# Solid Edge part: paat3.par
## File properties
Author: Mac
Template: Normal.par
Last saved by: Mac
Revision: 31
Application: Solid Edge
Material: Epoxy, cast rigid
Face Style: White
Fill Style: ANSI34(Plastic)
Virtual Style: Shiny resin yellow
Coef. of Thermal Exp: 5.9e-05
Thermal Conductivity: 2.1
Specific Heat: 0.0
Modulus of Elasticity: 3102640650.0
Poission's Ratio: 0.37
Yield Stress: 65500191.5
Ultimate Stress: 0.0
Elongation: 0.0
Density: 1300,000 kg/m^3
Accuracy: 0,990
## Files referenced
%..\..\Copy of copy of paat3\Asm15.asm
EC:\Documents and Settings\Mac\Desktop\Copy of copy of paat3\Asm15.asm
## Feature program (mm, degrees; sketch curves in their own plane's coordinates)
make body feature "unnamed MakeBodyFeature 1"
sketch for "ExtrudedProtrusion_1" plane through (11.3044, 0, -19.7548) normal (0, -1, 0) x-axis (1, 0, 0)
extrude "ExtrudedProtrusion_1" add finite 0.5 along +normal
sketch for "unnamed Cutout 1" plane through (12.2548, -0.5, -19.755) normal (0, -1, 0) x-axis (1, 0, 0)
extrude "unnamed Cutout 1" cut through along -normal
sketch for "ExtrudedCutout_5" plane through (11.3053, -0.5, -19.755) normal (0, -1, 0) x-axis (1, 0, 0)
extrude "ExtrudedCutout_5" cut finite 22 along -normal
sketch for "unnamed Cutout 2" plane through (-96.2523, 0, 0) normal (1, 0, 0) x-axis (0, 1, 0)
extrude "unnamed Cutout 2" cut along +normal
sketch for "unnamed Cutout 3" plane through (-96.2523, 0, 0) normal (1, 0, 0) x-axis (0, 1, 0)
extrude "unnamed Cutout 3" cut along +normal
sketch for "ExtrudedProtrusion_5" plane through (14.9994, 18.5539, 0) normal (0, 0, 1) x-axis (1, 0, 0)
extrude "ExtrudedProtrusion_5" add finite 0.2 along -normal
thinwall "Thinwall_9"  Thickness = 0.4 mm
sketch for "ExtrudedCutout_9" plane through (-89.4756, 0, 0) normal (1, 0, 0) x-axis (0, 1, 0)
extrude "ExtrudedCutout_9" cut finite 14.274 symmetric
sketch for "unnamed Cutout 4" plane through (-78.7952, 10.7, -24.5412) normal (0.989016, 0, 0.147809) x-axis (0, 1, 0)
  line (0.35, -2.7892) -> (0.35, -0.2935)
  arc centre (-0.99, -0.2935) radius 1.34 from (0.35, -0.2935) to (0.142, 0.4236) ccw
  arc centre (7.39, -0.2935) radius 1.34 from (6.258, 0.4236) to (6.05, -0.2935) ccw
  line (6.05, -2.7892) -> (6.05, -0.2935)
extrude "unnamed Cutout 4" cut through along -normal
body pattern "unnamed BodyPattern 1"
pattern "unnamed Pattern 1"
web network "WebNetwork_8"  Thickness = 0.4 mm
web network "WebNetwork_10"  Profile_Plane1_Distance = 27.6 mm; Thickness = 0.4 mm
sketch for "ExtrudedProtrusion_7" plane through (95.3651, -0.5, -15.3074) normal (0.9981, 0, -0.06161) x-axis (0, 1, 0)
extrude "ExtrudedProtrusion_7" add finite 0.4 along -normal
sketch for "ExtrudedCutout_14" plane through (-9.8993, 20.268, 8.0334) normal (-0.996876, 0, 0.078981) x-axis (0, -1, 0)
extrude "ExtrudedCutout_14" cut finite 8.6517 symmetric
web network "WebNetwork_11"  Profile_Plane1_Distance = 4 mm; Thickness = 1 mm
web network "WebNetwork_12"  Profile_Plane1_Distance = 2 mm; Thickness = 0.4 mm
web network "WebNetwork_13"  Profile_Plane1_Distance = 4 mm; Thickness = 1 mm
web network "WebNetwork_14"  Thickness = 1 mm; Profile_Plane1_Distance = 4 mm
sketch for "ExtrudedProtrusion_9" plane through (42.2932, -0.5, -28.6294) normal (0.06161, 0, 0.9981) x-axis (0, 1, 0)
  bspline degree 3 poles (-26.765, 35.525) (-25.9166, 30.6262) (-24.9611, 25.7482) (-22.7557, 16.0123) (-21.5039, 11.1594) (-19.3196, 3.9687) (-18.5369, 1.5903) (-16.8243, -3.1171) (-15.8984, -5.4454) (-14.3989, -8.89) (-13.88, -10.0297) (-12.8195, -12.2993) (-12.2779, -13.4293) (-11.2006, -15.693) (-10.6654, -16.827) (-9.646, -19.0945) (-9.1605, -20.2278) (-8.7078, -21.375) knots 0 0.2488 0.4996 0.625 0.7504 0.813 0.8757 0.9384 1 multiplicities 4 2 2 2 2 2 2 2 4
  line (-8.7078, -21.375) -> (8.7078, -21.375)
  bspline degree 3 poles (8.7078, -21.375) (9.1589, -20.2318) (9.6428, -19.1019) (10.1474, -17.9793) (10.6613, -16.836) (11.1969, -15.7009) (12.2754, -13.4345) (12.8178, -12.3029) (13.8789, -10.0321) (14.3977, -8.8927) (15.8947, -5.4541) (16.8174, -3.1346) (18.5242, 1.5539) (19.3052, 3.9242) (21.4857, 11.0943) (22.7397, 15.9462) (24.9544, 25.714) (25.9137, 30.6095) (26.765, 35.525) knots 0 0.2078 0.2608 0.3137 0.3666 0.4725 0.5783 0.79 1 multiplicities 4 3 2 2 2 2 2 2 4
  line (26.765, 35.525) -> (-26.765, 35.525)
extrude "ExtrudedProtrusion_9" add finite 0.4 along +normal
sketch for "unnamed Protrusion 1" #1 plane through (-2.0037, -0.5, -17.8799) normal (0.06161, 0, 0.9981) x-axis (0, 1, 0)
  line (28.15, 4.1934) -> (20.15, 4.1934)
  line (20.15, 4.1934) -> (20.15, -3.8066)
  line (20.15, -3.8066) -> (28.15, -3.8066)
  line (28.15, -3.8066) -> (28.15, 4.1934)
sketch for "unnamed Protrusion 1" #2 plane through (-2.0037, -0.5, -17.8799) normal (0.06161, 0, 0.9981) x-axis (0, 1, 0)
  line (-28.15, 4.2453) -> (-20.15, 4.2453)
  line (-20.15, 4.2453) -> (-20.15, -3.7547)
  line (-20.15, -3.7547) -> (-28.15, -3.7547)
  line (-28.15, -3.7547) -> (-28.15, 4.2453)
sketch for "unnamed Protrusion 1" #3 plane through (-2.0037, -0.5, -17.8799) normal (0.06161, 0, 0.9981) x-axis (0, 1, 0)
  line (13.55, 8.15) -> (-12.55, 8.15)
  line (-12.55, 8.15) -> (-12.55, -8.15)
  line (-12.55, -8.15) -> (13.55, -8.15)
  line (13.55, -8.15) -> (13.55, 8.15)
sketch for "unnamed Protrusion 1" #4 plane through (-2.0037, -0.5, -17.8799) normal (0.06161, 0, 0.9981) x-axis (0, 1, 0)
  line (31.8898, 9.35) -> (-31.8898, 9.35)
  bspline degree 3 poles (-31.8898, 9.35) (-31.494, 3.1414) (-30.9994, -3.0593) (-30.38, -9.25) knots 0 1 multiplicities 4 4
  line (30.38, -9.25) -> (-30.38, -9.25)
  bspline degree 3 poles (30.38, -9.25) (30.9994, -3.0593) (31.494, 3.1414) (31.8898, 9.35) knots 0 1 multiplicities 4 4
extrude "unnamed Protrusion 1" add finite 0.4 along +normal
sketch for "ExtrudedCutout_15" plane through (-53.1152, -0.5, -22.7401) normal (0.06161, 0, 0.9981) x-axis (0, 1, 0)
  line (13.55, -26.965) -> (-13.55, -26.965)
  line (-13.55, -26.965) -> (-13.55, -27.965)
  line (13.55, -27.965) -> (-13.55, -27.965)
  line (13.55, -26.965) -> (13.55, -27.965)
extrude "ExtrudedCutout_15" cut finite 6.11 along -normal
sketch for "unnamed Protrusion 2" plane through (-26.0789, -0.5, -30.5306) normal (0.06161, 0, 0.9981) x-axis (0, 1, 0)
  line (-13.55, 13.5) -> (-13.55, -13.6)
  line (-13.55, -13.6) -> (13.55, -13.6)
  line (13.55, 13.5) -> (13.55, -13.6)
  line (-13.55, 13.5) -> (13.55, 13.5)
extrude "unnamed Protrusion 2" add finite 0.4 along +normal
sketch for "unnamed Protrusion 3" #1 plane through (-38.2095, -0.5, -7.9303) normal (0.9981, 0, -0.06161) x-axis (0, 1, 0)
  bspline degree 3 poles (-29.8105, -17.9296) (-28.9987, -18.4378) (-28.1501, -18.8727) (-26.4544, -19.6431) (-25.6087, -19.9798) (-24.75, -20.2908) knots 0 0.5126 1 multiplicities 4 2 4
  line (-24.75, -15.7) -> (-24.75, -20.2908)
  line (-24.75, -15.7) -> (-24.75, 12.8808)
  line (-35.7137, 12.8808) -> (-24.75, 12.8808)
  bspline degree 3 poles (-35.7137, 12.8808) (-34.435, 2.7396) (-32.9833, -7.3799) (-31.2723, -17.4567) knots 0 1 multiplicities 4 4
  line (-30.5225, -17.4567) -> (-31.2723, -17.4567)
  arc centre (-21.3939, -4.4843) radius 15.8623 from (-30.5225, -17.4567) to (-29.8105, -17.9296) ccw
sketch for "unnamed Protrusion 3" #2 plane through (-38.2095, -0.5, -7.9303) normal (0.9981, 0, -0.06161) x-axis (0, 1, 0)
  bspline degree 3 poles (29.8105, -17.9296) (28.9987, -18.4378) (28.1501, -18.8727) (26.4544, -19.6431) (25.6087, -19.9798) (24.75, -20.2908) knots 0 0.5126 1 multiplicities 4 2 4
  line (24.75, -15.7) -> (24.75, -20.2908)
  line (24.75, -15.7) -> (24.75, 12.8808)
  line (24.75, 12.8808) -> (35.7137, 12.8808)
  bspline degree 3 poles (35.7137, 12.8808) (34.435, 2.7396) (32.9833, -7.3799) (31.2723, -17.4567) knots 0 1 multiplicities 4 4
  line (30.5225, -17.4567) -> (31.2723, -17.4567)
  arc centre (21.3939, -4.4843) radius 15.8623 from (30.5225, -17.4567) to (29.8105, -17.9296) cw
extrude "unnamed Protrusion 3" add finite 0.4 along +normal
sketch for "ExtrudedCutout_16" #1 plane through (-33.8579, 0, 0) normal (1, 0, 0) x-axis (0, 1, 0)
  line (-35.9773, 0) -> (-34.6634, 4.9035)
  line (-29.2434, 4.9035) -> (-34.6634, 4.9035)
  line (-29.2434, 4.9035) -> (-29.2434, -6.1165)
  line (-29.2434, -6.1165) -> (-20.8534, -6.1165)
  line (-20.8534, 6.609) -> (-20.8534, -6.1165)
  line (-37.8049, 6.609) -> (-20.8534, 6.609)
  line (-37.8049, 0) -> (-37.8049, 6.609)
  line (-37.8049, 0) -> (-35.9773, 0)
sketch for "ExtrudedCutout_16" #2 plane through (-33.8579, 0, 0) normal (1, 0, 0) x-axis (0, 1, 0)
extrude "ExtrudedCutout_16" cut through along -normal  Profile_Plane1_Distance = 33.8579 mm
sketch for "unnamed Protrusion 4" #1 plane through (-53.1192, -0.5, -22.7399) normal (0.06161, 0, 0.9981) x-axis (0.9981, 0, -0.06161)
  line (41.019, 13.6) -> (-0.981, 13.6)
  line (-0.981, 13.6) -> (-0.981, 23.7)
  line (-0.981, 23.7) -> (-41.0071, 23.7)
  bspline degree 3 poles (-41.0071, 23.7) (-40.8458, 25.9475) (-40.7162, 28.1972) (-40.6603, 30.4506) knots 0 1 multiplicities 4 4
  bspline degree 3 poles (-40.6603, 30.4506) (-40.6116, 30.7231) (-40.5173, 30.9865) (-40.3108, 31.3408) (-40.2292, 31.4544) (-40.0494, 31.655) (-39.9525, 31.7429) (-39.8446, 31.8177) knots 0 0.5034 0.7562 1 multiplicities 4 2 2 4
  bspline degree 3 poles (-39.8446, 31.8177) (-33.1015, 31.9753) (-26.357, 32.0744) (-12.8625, 32.1344) (-6.1128, 32.0952) (0.633, 31.9733) (5.063, 31.8932) (9.4918, 31.7775) (13.919, 31.6211) knots 0 0.3023 0.6049 1 multiplicities 4 2 3 4
  line (13.919, 24.7) -> (13.919, 31.6211)
  line (14.419, 24.7) -> (13.919, 24.7)
  line (14.419, 31.6033) -> (14.419, 24.7)
  bspline degree 3 poles (14.419, 31.6033) (16.5665, 31.5259) (18.7136, 31.4389) (20.8603, 31.3417) (27.5839, 31.0373) (34.3037, 30.6329) (41.019, 30.1039) knots 0 0.3847 1 multiplicities 4 3 4
  line (41.019, 30.1039) -> (41.019, 13.6)
sketch for "unnamed Protrusion 4" #2 plane through (-53.1192, -0.5, -22.7399) normal (0.06161, 0, 0.9981) x-axis (0.9981, 0, -0.06161)
  line (41.019, -13.6) -> (-0.981, -13.6)
  line (-0.981, -13.6) -> (-0.981, -23.7)
  line (-0.981, -23.7) -> (-41.0071, -23.7)
  bspline degree 3 poles (-41.0071, -23.7) (-40.8458, -25.9475) (-40.7162, -28.1972) (-40.6603, -30.4506) knots 0 1 multiplicities 4 4
  bspline degree 3 poles (-40.6603, -30.4506) (-40.6116, -30.7231) (-40.5173, -30.9865) (-40.3108, -31.3408) (-40.2292, -31.4544) (-40.0494, -31.655) (-39.9525, -31.7429) (-39.8446, -31.8177) knots 0 0.5034 0.7562 1 multiplicities 4 2 2 4
  bspline degree 3 poles (-39.8446, -31.8177) (-33.1015, -31.9753) (-26.357, -32.0744) (-12.8625, -32.1344) (-6.1128, -32.0952) (0.633, -31.9733) (5.063, -31.8932) (9.4918, -31.7775) (13.919, -31.6211) knots 0 0.3023 0.6049 1 multiplicities 4 2 3 4
  line (13.919, -24.7) -> (13.919, -31.6211)
  line (14.419, -24.7) -> (13.919, -24.7)
  line (14.419, -31.6033) -> (14.419, -24.7)
  bspline degree 3 poles (14.419, -31.6033) (16.5665, -31.5259) (18.7136, -31.4389) (20.8603, -31.3417) (27.5839, -31.0373) (34.3037, -30.6329) (41.019, -30.1039) knots 0 0.3847 1 multiplicities 4 3 4
  line (41.019, -30.1039) -> (41.019, -13.6)
extrude "unnamed Protrusion 4" add finite 0.4 along +normal
sketch for "ExtrudedProtrusion_17" #1 plane through (-66.6376, -0.5, -23.9092) normal (0.06161, 0, 0.9981) x-axis (0, 1, 0)
sketch for "ExtrudedProtrusion_17" #2 plane through (-66.6376, -0.5, -23.9092) normal (0.06161, 0, 0.9981) x-axis (0, 1, 0)
  line (-22.5, 12.2897) -> (-22.5, 27.8543)
  arc centre (-31.4275, 202.3937) radius 174.7676 from (-22.5, 27.8543) to (-23.55, 27.8038) cw
  line (-23.55, 27.8038) -> (-23.55, -12.2897)
  line (-23.55, -12.2897) -> (-18.3, -12.2897)
  line (-18.3, -12.2897) -> (-18.3, 12.2897)
  line (-18.3, 12.2897) -> (-22.5, 12.2897)
sketch for "ExtrudedProtrusion_17" #3 plane through (-66.6376, -0.5, -23.9092) normal (0.06161, 0, 0.9981) x-axis (0, 1, 0)
extrude "ExtrudedProtrusion_17" add finite 0.4 along +normal
sketch for "ExtrudedProtrusion_18" plane through (99.0219, 0, -21.1418) normal (0.118083, 0, -0.993004) x-axis (0.993004, 0, 0.118083)
extrude "ExtrudedProtrusion_18" add finite 0.4 along -normal
sketch for "unnamed Protrusion 5" plane through (-1.9791, -0.5, -17.4806) normal (0.06161, 0, 0.9981) x-axis (0, 1, 0)
extrude "unnamed Protrusion 5" add along +normal
sketch for "unnamed Protrusion 6" plane through (-1.9791, 8.6565, -17.4806) normal (0.06161, 0, 0.9981) x-axis (0, 1, 0)
extrude "unnamed Protrusion 6" add along +normal
sketch for "unnamed Cutout 5" plane through (70.2899, -0.5, -30.3576) normal (0.06161, 0, 0.9981) x-axis (0.988027, 0.141717, -0.060988)
extrude "unnamed Cutout 5" cut through along -normal
web network "WebNetwork_15"  Profile_Plane1_Distance = 16 mm; Thickness = 0.4 mm
sketch for "ExtrudedProtrusion_22" plane through (73.6314, -0.5, -14.1326) normal (0.06161, 0, 0.9981) x-axis (0, -1, 0)
  bspline degree 3 poles (-10.2443, 21.2648) (-11.2573, 19.6588) (-12.2012, 18.0207) (-13.9856, 14.6764) (-14.8249, 12.9695) (-17.2, 7.7826) (-18.5943, 4.2368) (-20.4779, -1.1786) (-21.0698, -2.9976) (-21.6297, -4.8256) (-21.6303, -4.8275) (-21.6308, -4.8293) knots 0 0.1984 0.3988 0.7995 0.9998 1 multiplicities 4 2 2 2 2 4
  arc centre (0.06, 5.4788) radius 24.0156 from (-21.6308, -4.8293) to (21.6775, -4.9821) ccw
  bspline degree 3 poles (21.6775, -4.9821) (21.6614, -4.9293) (21.6453, -4.8765) (21.0698, -2.9976) (20.4779, -1.1786) (18.5943, 4.2368) (17.2, 7.7826) (14.8249, 12.9695) (13.9856, 14.6764) (12.2012, 18.0207) (11.2573, 19.6588) (10.2443, 21.2648) knots 0 0.0058 0.205 0.6034 0.8027 1 multiplicities 4 2 2 2 2 4
  line (10.2443, 21.2648) -> (-10.2443, 21.2648)
extrude "ExtrudedProtrusion_22" add finite 0.4 along +normal
Other named dimensions: "KeypointCurve_37": StartDerivMagnitude = 46.4677 mm | "ExtrudedSurface_3": FiniteDepth = 39.0046 mm | "KeypointCurve_41": StartDerivMagnitude = 37.6646 mm; EndDerivMagnitude = -37.6646 mm | "OffsetSurface_2": Distance = 1 mm | "KeypointCurve_43": StartDerivMagnitude = -2.0329 mm; EndDerivMagnitude = -2.0329 mm | "OffsetSurface_3": Distance = 0.1 mm | "OffsetSurface_4": Distance = 0.1 mm
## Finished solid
Body 1: sheet body, 1 face, 4 edges, 4 vertices.
  Faces by surface: plane 1
  Edges by curve: line 4
Body 2: sheet body, 2 faces, 11 edges, 9 vertices.
  Faces by surface: offset 2
  Edges by curve: curve on surface 9, line 2
Body 3: solid body, 697 faces, 1906 edges, 1229 vertices, 9 internal voids.
  Faces by surface: plane 471, offset 151, swept 30, cylinder 25, spline 20
  Edges by curve: line 1076, intersection 608, curve on surface 90, spline 88, circle 40, ellipse 4
Body 4: solid body, 11 faces, 27 edges, 18 vertices.
  Faces by surface: spline 8, plane 2, swept 1
  Edges by curve: curve on surface 22, spline 4, line 1
Body 5: sheet body, 1 face, 4 edges, 4 vertices.
  Faces by surface: offset 1
  Edges by curve: curve on surface 4
Body 6: sheet body, 1 face, 4 edges, 4 vertices.
  Faces by surface: swept 1
  Edges by curve: line 2, spline 2
Body 7: sheet body, 1 face, 4 edges, 4 vertices.
  Faces by surface: spline 1
  Edges by curve: spline 4
Bounding box of the edges (mm; curved faces can reach further): 218.786 x 76.107 x 44.412, from (-97.5583, -37.1023, -39.5084) to (121.2272, 39.0046, 4.9035).
Cylindrical faces by radius (mm): R0.7 x1, R1.2274 x1, R1.34 x4, R2 x1, R2.4 x1, R2.85 x2, R3.62 x2, R8 x2, R15.8623 x2, R24.0156 x1, R123 x2, R124.3034 x2, R174.7676 x2, R9368.3842 x2
Planar faces by outward normal: +y 64, +z 12, -y 63, -z 7, oblique 327
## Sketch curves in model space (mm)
line (94.957, 0, -21.6252) -> (103.0867, 0, -20.6585)
spline (-11.0191, 28.0493, -6.1) -> (-10.5833, 28.0395, -0.6) -> (-10.1476, 28.0294, 4.9)
spline (-11.0191, -29.0493, -6.1) -> (-10.5833, -29.0395, -0.6) -> (-10.1476, -29.0294, 4.9)
line (-11.0191, -0.5, -6.1) -> (-11.0191, -29.0493, -6.1)
line (-11.0191, -0.5, -6.1) -> (-11.0191, 28.0493, -6.1)
line (-78.0563, 0, -28.1325) -> (-79.7064, 0, -17.0911)
line (-94.6106, 0, -16.1711) -> (98.6828, 0, -28.1026)
line (-90, 0, 0) -> (-86.6044, 0, 0)
spline (-90, 0, 0) -> (-95.5426, 0, -13.4256) -> (-97.3884, 0, -36.2684)
line (-97.3884, 0, -36.2684) -> (66.9645, 0, -39.4938)
line (-97.3884, -0.5, -36.2684) -> (-77.3884, -0.5, -36.6609)
line (-77.3884, -0.5, -36.6609) -> (-80.8989, -0.5, -13.1711)
line (-95.4902, -0.5, -13.1711) -> (-80.8989, -0.5, -13.1711)
spline (-95.4902, -0.5, -13.1711) -> (-96.9145, -0.5, -23.5092) -> (-97.3884, -0.5, -36.2684)
arc centre (-79.7976, 27.0681, 0) radius 7 from (-80.0751, 34.0626, 0) through (-84.2397, 32.4781, 0) to (-86.6044, 28.7016, 0)
arc centre (33, -0.0002, 0) radius 123 from (-90, 0, 0) through (-89.1481, 14.4509, 0) to (-86.6044, 28.7016, 0)
line (119.9998, 0, 0) -> (-90, 0, 0)
spline (119.9998, 0, 0) -> (59.233, 29.0897, 0) -> (-80.0751, 34.0626, 0)
line (-97.3884, 0, -36.2684) -> (66.9645, 0, -39.4938)
spline (99.266, 0, -26.5171) -> (84.61, 0, -36.757) -> (66.9645, 0, -39.4938)
arc centre (-79.1474, 9.71, -24.8906) radius 1.34 from (-79.1474, 11.05, -24.8906) through (-79.2026, 10.9969, -24.5214) to (-79.2534, 10.842, -24.1814)
arc centre (-79.5398, 13.9, -22.2654) radius 3.62 from (-79.2534, 10.842, -24.1814) through (-80.0748, 13.9, -18.6852) to (-79.2534, 16.958, -24.1814)
arc centre (-79.1474, 18.09, -24.8906) radius 1.34 from (-79.2534, 16.958, -24.1814) through (-79.2026, 16.8031, -24.5214) to (-79.1474, 16.75, -24.8906)
line (-79.1474, 16.75, -24.8906) -> (-78.7785, 16.75, -27.3589)
arc centre (-78.7785, 13.9, -27.3589) radius 2.85 from (-78.7785, 16.75, -27.3589) through (-78.3575, 13.8155, -30.1763) to (-78.7785, 11.05, -27.3589)
line (-78.7785, 11.05, -27.3589) -> (-79.1474, 11.05, -24.8906)
line (99.266, 0, -26.5171) -> (-99.1293, 0, -26.5171)
spline (99.266, 0, -26.5171) -> (29.3381, 25.2853, -26.5171) -> (-97.0225, 31.0594, -26.5171)
arc centre (130.8707, 0, -26.5171) radius 230 from (-97.0225, 31.0594, -26.5171) through (-98.602, 15.5654, -26.5171) to (-99.1293, 0, -26.5171)
spline (-97.5583, 0, -24.48) -> (3.7061, 0, -26.1906) -> (103.7269, 0, -21.1088)
arc centre (-112.8057, 23.422, 0) radius 9 from (-121.612, 25.2789, 0) through (-121.6121, 25.2785, 0) to (-121.6122, 25.2782, 0)
arc centre (-79.7976, 27.0687, 0) radius 7 from (-80.0751, 34.0632, 0) through (-84.2397, 32.4787, 0) to (-86.6043, 28.7022, 0)
arc centre (33, 0.0002, 0) radius 123 from (-90, 0.0002, 0) through (-89.1481, 14.4513, 0) to (-86.6043, 28.7022, 0)
arc centre (33, 0.0002, 0) radius 123 from (-90, 0.0002, 0) through (-88.8069, -17.0899, 0) to (-85.2508, -33.8486, 0)
spline (120, 0.0003, 0) -> (57.7847, -29.3324, 0) -> (-85.2508, -33.8486, 0)
spline (120, 0.0003, 0) -> (59.2334, 29.0903, 0) -> (-80.0751, 34.0632, 0)
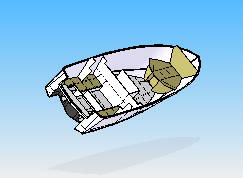
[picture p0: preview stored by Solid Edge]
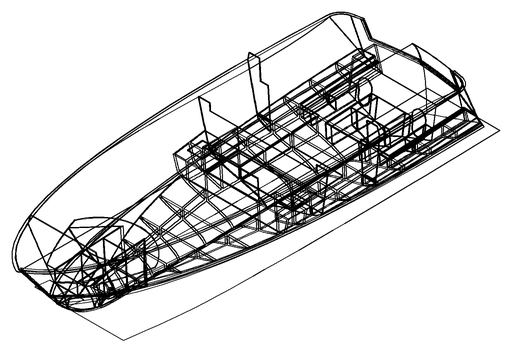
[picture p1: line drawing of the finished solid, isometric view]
